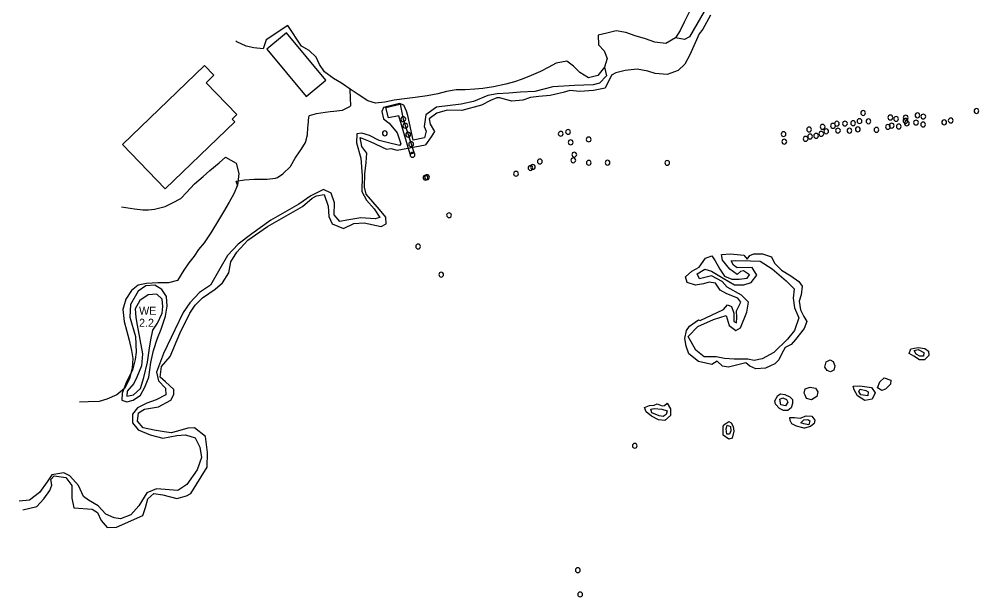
# Model space of a CAD drawing. Extents: x 2160437 to 2172832, y 205694 to 212444.
# Drawn here: x 2160437 to 2161037, y 210691 to 211052 of the extents above; entities that cross this region are included whole.
import ezdxf

# ---------------------------------------------------------------- set-up
doc = ezdxf.new("R2010")
doc.units = 0
for name, color, linetype in [('Default', 7, 'Continuous'), ('RD_EX_Bldg', 7, 'Continuous'), ('RD_EX_BldgApp', 7, 'Continuous'), ('RD_EX_Dam', 7, 'Continuous'), ('RD_EX_H2O', 7, 'Continuous'), ('RD_EX_H2O_Pond', 7, 'Continuous'), ('RD_EX_H2O_txCode', 7, 'Continuous'), ('RD_EX_Road_Post', 7, 'Continuous'), ('RD_EX_VEG_ShrubLine', 7, 'Continuous'), ('RD_EX_VEG_TreeLine', 7, 'Continuous')]:
    doc.layers.add(name, color=color, linetype=linetype)

# ---------------------------------------------------------------- blocks, each defined once
blk = doc.blocks.new('POST')
at = {"layer": 'Default'}
for start, end in [(90, 270), (270, 90)]:
    blk.add_arc((0, 0), 0.0417, start, end, dxfattribs=at)

msp = doc.modelspace()

# ---------------------------------------------------------------- linework, layer by layer
at = {"layer": 'RD_EX_Bldg'}
msp.add_lwpolyline([(2160501.36, 210973.72), (2160552.58, 211023.14), (2160558.56, 211016.94), (2160553.68, 211012.23), (2160572.82, 210992.39), (2160569.87, 210989.54), (2160571.52, 210987.83), (2160528.14, 210945.96)], close=True, dxfattribs=at)
at = {"layer": 'RD_EX_BldgApp'}
msp.add_lwpolyline([(2160591.54, 211033.38), (2160616.14, 211003.75), (2160628.41, 211013.91), (2160603.81, 211043.54)], close=True, dxfattribs=at)
at = {"layer": 'RD_EX_Dam'}
msp.add_lwpolyline([(2160665.9, 210996.74), (2160674.86, 210998.85), (2160676.88, 210989.52), (2160683.57, 210968.33), (2160681.23, 210967.59), (2160674.11, 210991.64), (2160667.59, 210990.28)], close=True, dxfattribs=at)
at = {"layer": 'RD_EX_H2O'}
for points in [[(2160868.85, 211054.5), (2160864.01, 211045.74), (2160861.74, 211042.89), (2160855.94, 211029.7), (2160852.83, 211023.99), (2160848.57, 211019.95), (2160841.71, 211017.45), (2160834.34, 211018.06), (2160829.6, 211019.63), (2160823.02, 211020.81), (2160815.45, 211019.96), (2160809.7, 211018.51), (2160806.97, 211016.96), (2160803.03, 211008.9), (2160795.67, 211007.37), (2160787.27, 211006.83), (2160780.89, 211007.46), (2160776.83, 211006.17), (2160768.71, 211004.35), (2160761.67, 211003.77), (2160756.27, 211003.09), (2160751.54, 211001.35), (2160744.74, 211000.78), (2160740.76, 211001.83), (2160737.25, 211002.9), (2160735.24, 211002.82), (2160731.34, 211001.23), (2160725.76, 210998.26), (2160713.38, 210994.95), (2160704.23, 210995.09), (2160697.93, 210993.2), (2160693.13, 210989.75), (2160693.61, 210986.47), (2160696.31, 210981.78), (2160694.27, 210978.42), (2160690.79, 210973.58)], [(2160439.11, 210745.33), (2160447.81, 210747.53), (2160452.24, 210752.19), (2160456, 210757.43), (2160457.31, 210760.83), (2160456.66, 210764.25), (2160458.64, 210766.72), (2160465.96, 210765.49), (2160469.83, 210760.6), (2160469.81, 210752.74), (2160470.94, 210746.67), (2160482.54, 210745.7), (2160485.88, 210743.73), (2160488.03, 210738.76), (2160491.77, 210734.23), (2160497.77, 210734.58), (2160514.12, 210741.77), (2160515.69, 210746.79), (2160517.21, 210752.3), (2160521, 210755.68), (2160526.7, 210754.72), (2160535.43, 210752.39), (2160541.41, 210754.2), (2160544.21, 210755.65), (2160554.34, 210772.02), (2160554.53, 210781.26), (2160553.3, 210791.2), (2160546.51, 210796.54), (2160542.19, 210796.35), (2160535.79, 210794.61), (2160531.79, 210793.59), (2160527.47, 210794.15), (2160521.27, 210795.16), (2160514.35, 210796.62), (2160510.71, 210800.87), (2160511.34, 210805.97), (2160515.24, 210808.32), (2160523.83, 210809.76), (2160531.71, 210814), (2160533.49, 210817.54), (2160533.47, 210820.56), (2160528.26, 210825.3), (2160524.96, 210828.24), (2160525.84, 210834.91), (2160531.19, 210841.23), (2160537.3, 210855.49), (2160543.39, 210868.31), (2160546.86, 210873.28), (2160551.36, 210877.96), (2160559.3, 210883.23), (2160564, 210887.35), (2160567.8, 210893.56), (2160569.05, 210900.41), (2160572.9, 210906.49), (2160579.81, 210913.95), (2160592.04, 210922.54), (2160613.97, 210935.03), (2160619.93, 210940.26), (2160622.57, 210941.61), (2160627.52, 210942.44), (2160629.93, 210935.1), (2160630.36, 210928.76), (2160632.34, 210924.05), (2160639.43, 210921.18), (2160645.94, 210924.43), (2160652.52, 210924.75), (2160663.14, 210922.37), (2160666.23, 210924.22), (2160665.96, 210928.34), (2160662.09, 210933.1), (2160653.6, 210942.62), (2160652.67, 210947.09), (2160652.83, 210955.36), (2160653.62, 210962.36), (2160654.13, 210968.21), (2160651.06, 210972.55), (2160649.9, 210978.06), (2160656.09, 210975.6), (2160666.29, 210970.75), (2160669.14, 210971.31), (2160673.11, 210970.09), (2160690.79, 210973.58)]]:
    msp.add_lwpolyline(points, dxfattribs=at)
for points in [[(2160903.23, 210833.84), (2160897.1, 210833.6), (2160893.47, 210835.1), (2160890.9, 210837.17), (2160880.15, 210834.53), (2160876.29, 210835.15), (2160873.04, 210838.33), (2160869.61, 210836.26), (2160861.35, 210837.98), (2160855.27, 210842.82), (2160853.58, 210847.61), (2160852.9, 210852.49), (2160853.87, 210857.52), (2160855.72, 210860.19), (2160861.28, 210864.22), (2160862.48, 210863.81), (2160876.88, 210870.53), (2160879.57, 210873.54), (2160882.04, 210872.42), (2160883.47, 210868.27), (2160883.52, 210863.15), (2160885.05, 210862.17), (2160885.33, 210865.48), (2160885.16, 210869.82), (2160887.9, 210875.12), (2160885.84, 210877.73), (2160879.1, 210880.44), (2160874.92, 210882.59), (2160871.99, 210886.99), (2160867.98, 210887.65), (2160864.37, 210886.65), (2160859.42, 210885.88), (2160854.26, 210887.46), (2160853.25, 210890.99), (2160857.22, 210894.57), (2160861.68, 210897.07), (2160865.82, 210902.64), (2160869.65, 210904.12), (2160871.75, 210901.08), (2160874.59, 210895.71), (2160877.67, 210891.33), (2160882.15, 210889.59), (2160886.78, 210889.64), (2160891.75, 210890.26), (2160893.13, 210892.24), (2160889.54, 210894.85), (2160887.54, 210894.39), (2160885.56, 210892.51), (2160880.86, 210895.82), (2160876.38, 210901.47), (2160875.76, 210904.88), (2160881.36, 210905.3), (2160889.63, 210904.57), (2160891.66, 210902.02), (2160893.46, 210904.28), (2160895.87, 210905.3), (2160901.4, 210905.31), (2160906.96, 210903.58), (2160908.85, 210899.45), (2160913.24, 210895.21), (2160918.95, 210891.69), (2160923.96, 210888.12), (2160926.14, 210885.25), (2160925.49, 210879.73), (2160924.34, 210875.79), (2160925.14, 210870.33), (2160927.17, 210866.31), (2160928.95, 210863.13), (2160927.35, 210858.79), (2160921.97, 210851.76), (2160919.33, 210848.61), (2160915.47, 210846.74), (2160913.47, 210843.16), (2160911.48, 210839.08), (2160909, 210836.67), (2160906.4, 210835.33)], [(2160993, 210843.11), (2160994.06, 210846.1), (2160998.52, 210846.86), (2161002.7, 210846.25), (2161005.08, 210844.59), (2161005.2, 210841.93), (2161002.48, 210839.11), (2160999.39, 210839.06), (2160995.94, 210841.43)], [(2160940.2, 210834.59), (2160941.14, 210837.81), (2160943.59, 210839.13), (2160945.43, 210838.07), (2160946.62, 210835.45), (2160946.01, 210832.71), (2160943.88, 210831.59), (2160941.66, 210832.42)], [(2160974.74, 210825.43), (2160977.34, 210827.96), (2160981.58, 210826.33), (2160981.32, 210823.84), (2160978.16, 210820.82), (2160975.82, 210820.02), (2160973.21, 210821.67)], [(2160927.44, 210818.24), (2160927.99, 210821.06), (2160931.05, 210821.94), (2160934.36, 210821.39), (2160936.01, 210819.02), (2160935.34, 210816.26), (2160931.98, 210814.13), (2160928.8, 210814.93), (2160927.92, 210817.01)], [(2160962.17, 210822.87), (2160969.42, 210821.76), (2160971.8, 210818.51), (2160969.77, 210814.48), (2160965.37, 210813.78), (2160960.67, 210816.57), (2160958.57, 210820.36), (2160957.96, 210822.6)], [(2160909.13, 210813.56), (2160911.01, 210816.82), (2160912.67, 210817.81), (2160915.27, 210817.47), (2160918.36, 210815.98), (2160920.04, 210814.32), (2160920.13, 210811.88), (2160919.27, 210809.15), (2160917.14, 210807.39), (2160914.46, 210807.36), (2160911.97, 210808.77), (2160909.44, 210811.48)], [(2160835.56, 210811.54), (2160838.55, 210810.47), (2160840.14, 210810.59), (2160841.75, 210812.03), (2160843.9, 210808.54), (2160843.86, 210804.3), (2160840.41, 210801.15), (2160836.32, 210801.58), (2160832.04, 210803.84), (2160828.75, 210806.6), (2160827.53, 210809.29), (2160830.73, 210810.6), (2160833.65, 210810.84)], [(2160927.44, 210796.5), (2160922.6, 210797.59), (2160919.72, 210799.04), (2160918.62, 210801.13), (2160918.43, 210803.01), (2160921.3, 210803.16), (2160924.85, 210802.74), (2160928.54, 210804.05), (2160932.26, 210803.96), (2160934.14, 210801.46), (2160933.56, 210799.23), (2160931.25, 210797.38), (2160927.56, 210796.45)], [(2160880.22, 210800.52), (2160881.84, 210799.67), (2160882.94, 210797.49), (2160883.35, 210794.44), (2160882.3, 210790.08), (2160880.27, 210789.64), (2160876.71, 210792), (2160876.82, 210797.6), (2160877.8, 210798.87)]]:
    msp.add_lwpolyline(points, close=True, dxfattribs=at)
at = {"layer": 'RD_EX_H2O_Pond'}
msp.add_lwpolyline([(2160526.57, 210872.54), (2160526.26, 210877.02), (2160522.92, 210880.13), (2160517.42, 210879.69), (2160512.18, 210876.25), (2160509.42, 210871.04), (2160509.75, 210865.62), (2160510.61, 210860.83), (2160513.95, 210842.93), (2160513.3, 210835.43), (2160510.43, 210828.19), (2160508.52, 210824.3), (2160504.28, 210819.54), (2160504.03, 210816.43), (2160508.21, 210817.15), (2160512.69, 210821.17), (2160514.71, 210828.05), (2160517.13, 210837.75), (2160518.36, 210846.34), (2160519.18, 210851.68), (2160520.43, 210857.63), (2160523.31, 210862.08), (2160526.21, 210868.27)], close=True, dxfattribs=at)
at = {"layer": 'RD_EX_VEG_ShrubLine'}
for points in [[(2160867.24, 211060.84), (2160855.8, 211040.94), (2160852.66, 211039.38), (2160846.9, 211040.46)], [(2160802.51, 211021.99), (2160803.81, 211016.54), (2160799.48, 211011.96), (2160795.6, 211010.94), (2160783.81, 211010.48), (2160770.23, 211009.79), (2160759.18, 211006.87), (2160750.08, 211006.47), (2160742.79, 211005.72), (2160735.57, 211005.39), (2160729.76, 211004.32), (2160720.67, 211000.5), (2160713.04, 210998.86), (2160697.67, 210997.02), (2160691.01, 210992.16), (2160689.93, 210985.05), (2160691.23, 210982.05), (2160690.11, 210977.94), (2160683.1, 210976.52), (2160680.72, 210986.97), (2160679.73, 210991.82), (2160678.78, 210994.45), (2160677.15, 210998.26), (2160674.41, 210999.38), (2160664.47, 210996.87), (2160663.37, 210994.3), (2160664.44, 210989.65), (2160668.02, 210987.04), (2160672.95, 210980.93), (2160675.29, 210974.08), (2160674.52, 210973.15), (2160666.73, 210975), (2160661.73, 210976.23), (2160655.8, 210979.26), (2160651.02, 210980.73), (2160647.75, 210980.29), (2160647.68, 210974.76), (2160650.32, 210965.11), (2160651.24, 210954.1), (2160650.91, 210944.29), (2160653.91, 210938.88), (2160658.67, 210933.53), (2160662.32, 210928.17), (2160659.28, 210927.35), (2160650.31, 210927.88), (2160641.54, 210926.41), (2160637.2, 210925.53), (2160633.74, 210929.65), (2160633.92, 210937.21), (2160631.82, 210943.32), (2160627.11, 210945.57), (2160619.02, 210941.64), (2160611.64, 210936.47), (2160594.03, 210926.49), (2160582.13, 210917.86), (2160573.75, 210911.52), (2160567.09, 210904.35), (2160562.31, 210895.97), (2160556.42, 210885.78), (2160549.51, 210881.26), (2160543.53, 210874.7), (2160539.39, 210868.76), (2160534.02, 210857.81), (2160526.99, 210843.04), (2160522.64, 210831.4), (2160523.94, 210825.95), (2160528.25, 210821.39), (2160528.54, 210817.32), (2160522.38, 210814.2), (2160516.63, 210812.11), (2160510.79, 210809.2), (2160507.74, 210805.14), (2160507.64, 210799.79), (2160511.23, 210795.33), (2160518.69, 210792.24), (2160526.59, 210790.23), (2160535.4, 210791.91), (2160540.86, 210792.34), (2160546.77, 210790.3), (2160549.69, 210784.46), (2160550.79, 210778.05), (2160547.98, 210770.46), (2160541.71, 210761.2), (2160535.97, 210757.37), (2160522.64, 210758.48), (2160516.55, 210755.91), (2160511.61, 210747.95), (2160506.52, 210742.33), (2160500.24, 210739.72), (2160496.18, 210740.35), (2160491.01, 210742.75), (2160486.3, 210747.95), (2160486.3, 210747.95), (2160480.27, 210751.38), (2160477.08, 210753.69), (2160473.82, 210760.55), (2160468.56, 210766.7), (2160464.66, 210768.58), (2160457.18, 210767.16), (2160454.29, 210762.96), (2160449.58, 210756.12), (2160443.24, 210751.35), (2160436.86, 210750.82)], [(2160573.36, 210948.21), (2160572.45, 210950.69), (2160577.7, 210951.67), (2160583.63, 210952.11), (2160590.63, 210952.07), (2160591.81, 210952), (2160596.96, 210952.63), (2160598.17, 210953), (2160601.69, 210955.29), (2160606.42, 210959.98), (2160606.55, 210960.39), (2160609.29, 210965.17), (2160612.54, 210969.78), (2160613.08, 210970.58), (2160615.74, 210974.93), (2160615.74, 210974.93), (2160617.02, 210979.8), (2160617.29, 210984.36), (2160617.39, 210985.59), (2160617.91, 210990.98), (2160618.21, 210991.77), (2160622.55, 210993.16), (2160622.55, 210993.16), (2160628, 210993.82), (2160631.27, 210994.37), (2160633.41, 210994.5), (2160638.79, 210995.13), (2160638.79, 210995.13), (2160643.54, 210997.56), (2160644.11, 210998.05), (2160643.81, 211002.76), (2160643.77, 211008.29)]]:
    msp.add_lwpolyline(points, dxfattribs=at)
for points in [[(2160899.8, 210900.89), (2160907.31, 210895.99), (2160916.13, 210888.59), (2160921.18, 210883.47), (2160920.44, 210877.67), (2160921.4, 210871.67), (2160923.95, 210865.42), (2160921.33, 210857.54), (2160917.04, 210852.03), (2160908.51, 210843.62), (2160901.16, 210839.68), (2160896.04, 210838.79), (2160892.23, 210839.57), (2160883.73, 210839.55), (2160877.56, 210839.89), (2160872.4, 210841), (2160864.86, 210841.02), (2160859.65, 210845.17), (2160854.94, 210853.72), (2160860.89, 210859.99), (2160870.62, 210864.37), (2160878.64, 210866.87), (2160880.61, 210860.59), (2160884.62, 210857.36), (2160887.67, 210859.1), (2160891.45, 210868.9), (2160892.56, 210875.1), (2160888.2, 210879.44), (2160879.23, 210884.63), (2160876.09, 210888.13), (2160869.41, 210891.72), (2160861.9, 210889.74), (2160860.56, 210892.8), (2160865.25, 210895.87), (2160869.38, 210894.57), (2160876.74, 210890.19), (2160883.91, 210886), (2160889.76, 210886), (2160894.17, 210887.4), (2160897.72, 210892.12), (2160894.96, 210896.86), (2160885.61, 210896.65), (2160883.32, 210898.26), (2160881.83, 210901.01), (2160884.78, 210901.28), (2160893.83, 210901.05)], [(2160506.43, 210873.61), (2160506.02, 210865.8), (2160509.6, 210853.75), (2160510.05, 210843.88), (2160509.33, 210839.34), (2160507.62, 210832.76), (2160503.87, 210825.36), (2160501.23, 210818.27), (2160501.05, 210813.9), (2160504.09, 210812.81), (2160508.15, 210813.98), (2160512.69, 210817.08), (2160515.33, 210822.03), (2160517.9, 210828.33), (2160519.08, 210837.47), (2160520.71, 210844.9), (2160523.24, 210852.67), (2160525.5, 210858.31), (2160528.36, 210866.4), (2160529.3, 210872.69), (2160528.88, 210878.67), (2160525.97, 210883), (2160521.66, 210885.88), (2160515.96, 210885.45), (2160511.3, 210881.94)], [(2160996.12, 210844.91), (2160998.68, 210845.55), (2161002.25, 210843.65), (2161001.96, 210841.32), (2160999.65, 210841.43), (2160997.4, 210842.73)], [(2160962.75, 210817.27), (2160961.55, 210819.41), (2160962.42, 210820.72), (2160965.99, 210820.04), (2160967.45, 210819.1), (2160967.08, 210816.62)], [(2160912.73, 210811.03), (2160912.24, 210814.55), (2160913.99, 210815.27), (2160916.33, 210814.4), (2160917.16, 210812.7), (2160915.67, 210810.45)], [(2160836.68, 210804.03), (2160832.22, 210806.05), (2160831.52, 210808.26), (2160833.65, 210808.8), (2160838.52, 210808.29), (2160841.67, 210807.34), (2160841.07, 210804.97), (2160839.31, 210803.78)], [(2160925.25, 210799.7), (2160927.21, 210801.54), (2160929.7, 210801.83), (2160931.01, 210800.96), (2160930.29, 210798.55), (2160927.12, 210799.04)], [(2160878.99, 210792.61), (2160878.59, 210796.1), (2160879.23, 210798.35), (2160881.31, 210797.51), (2160881.49, 210794.78), (2160880.76, 210792.75)]]:
    msp.add_lwpolyline(points, close=True, dxfattribs=at)
at = {"layer": 'RD_EX_VEG_TreeLine'}
for points in [[(2160855.5, 211056.38), (2160852.29, 211050.07), (2160849.79, 211045.06), (2160846.9, 211040.46), (2160840.85, 211036.83), (2160834.16, 211037.66), (2160828.23, 211039.65), (2160821.87, 211041.72), (2160815.9, 211043.61), (2160809.95, 211044.8), (2160804.15, 211043.26), (2160798.58, 211041.96), (2160798.86, 211035.92), (2160802.5, 211032.19), (2160804.29, 211027.44), (2160802.51, 211021.99), (2160798.46, 211016.88), (2160792.57, 211015.38), (2160787.2, 211018.62), (2160783.22, 211022.62), (2160779.13, 211025.86), (2160772.48, 211024.47), (2160767.39, 211021.92), (2160762.62, 211019.32), (2160756.86, 211016.84), (2160751.15, 211014.45), (2160746.29, 211012.94), (2160741.01, 211011.51), (2160741.01, 211011.51), (2160733.15, 211009.74), (2160726.57, 211008.78), (2160721.49, 211008.3), (2160715.61, 211007.84), (2160709.94, 211007.85), (2160703.98, 211006.73), (2160698.42, 211005.43), (2160691.81, 211004.14), (2160684.34, 211003), (2160679.36, 211002.48), (2160671.13, 211001.45), (2160665.37, 211000.24), (2160659.45, 210999.45), (2160654.67, 211000.91), (2160648.71, 211004.89), (2160643.77, 211008.29), (2160638.24, 211011.95), (2160633.31, 211014.87), (2160627.62, 211019.19), (2160624.49, 211023.63), (2160622.5, 211028.34), (2160618.09, 211032.54), (2160613.34, 211035.21), (2160604.81, 211048.09), (2160591.23, 211039.08), (2160589.29, 211033.53), (2160583.51, 211034.07), (2160578.6, 211035.25), (2160572.93, 211037.81), (2160572.15, 211038.4)], [(2160500.87, 210934.7), (2160508.85, 210933.4), (2160514.07, 210932.89), (2160517.75, 210932.85), (2160521.42, 210933.27), (2160528.01, 210935.03), (2160532.69, 210937.2), (2160537.88, 210939.95), (2160541.46, 210943.77), (2160546.35, 210949.2), (2160551.8, 210953.8), (2160556.04, 210957.55), (2160561.81, 210962.35), (2160565.88, 210965.72), (2160572.35, 210962.1), (2160574.16, 210955.6), (2160573.36, 210948.21), (2160570.96, 210942.92), (2160568.1, 210937.61), (2160564.45, 210931.62), (2160561.44, 210926.5), (2160556.55, 210918.52), (2160552.45, 210912.27), (2160548.97, 210908.17), (2160546.11, 210903.9), (2160542.96, 210899.77), (2160539.7, 210895.11), (2160535.88, 210888.73), (2160530.13, 210887.28), (2160523.42, 210887.31), (2160516.5, 210886.85), (2160511.29, 210885.85), (2160506.99, 210882.47), (2160503.56, 210876.96), (2160501.69, 210870.51), (2160502.53, 210863.18), (2160503.88, 210857.7), (2160505.58, 210851.49), (2160507.01, 210844.93), (2160507.91, 210840.01), (2160507.53, 210834.04), (2160505.71, 210827.22), (2160502.68, 210821.3), (2160497.83, 210817.24), (2160491.65, 210814.59), (2160486.84, 210813.18), (2160479.96, 210812.82), (2160474.58, 210812.71)]]:
    msp.add_lwpolyline(points, dxfattribs=at)

# ---------------------------------------------------------------- block references
at = {"layer": 'RD_EX_Road_Post', "xscale": 36, "yscale": 36}
for p in [(2160964.21, 210993.42), (2160998.17, 210991.94), (2161035.01, 210994.66), (2160676.88, 210989.52), (2160676.88, 210989.52), (2160678.17, 210985.43), (2160945.39, 210985.38), (2160947.84, 210986.7), (2160952.87, 210986.8), (2160957.96, 210987.04), (2160961.97, 210988.35), (2160967.52, 210988.22), (2160981.22, 210990.58), (2160982.05, 210985.51), (2160984.82, 210989.71), (2160990.7, 210988.49), (2160990.79, 210990.48), (2160991.54, 210986.9), (2160997.28, 210987.42), (2161001.69, 210986.18), (2161001.81, 210991.16), (2161014.89, 210987.56), (2161018.95, 210988.73), (2160665.35, 210980.69), (2160679.94, 210979.84), (2160775.26, 210980.42), (2160779.84, 210981.59), (2160914.5, 210980.2), (2160930.46, 210983.11), (2160938.08, 210980.35), (2160938.9, 210984.73), (2160941.18, 210981.96), (2160948.5, 210982.41), (2160955.66, 210982.35), (2160960.89, 210983.17), (2160972.52, 210982.88), (2160979.72, 210984.72), (2160986.49, 210984.95), (2160681.8, 210973.92), (2160781.46, 210975.06), (2160792.7, 210976.87), (2160914.96, 210975.48), (2160928.28, 210977.26), (2160931.08, 210978.72), (2160934.84, 210979.1), (2160783.72, 210967.38), (2160682.65, 210967.23), (2160762.21, 210963.11), (2160783.1, 210963.84), (2160792.77, 210962.3), (2160804.54, 210962.35), (2160841.83, 210962.2), (2160747.32, 210955.43), (2160756.32, 210959.06), (2160757.86, 210959.64), (2160690.78, 210952.96), (2160691.74, 210953.3), (2160705.47, 210929.5), (2160686.13, 210909.94), (2160700.59, 210892.39), (2160821.51, 210785.41), (2160785.97, 210707.69), (2160787.38, 210692.51)]:
    msp.add_blockref('POST', p, dxfattribs=at)

# ---------------------------------------------------------------- texts
at = {"layer": 'RD_EX_H2O_txCode'}
for s, p in [('WE', (2160511.78, 210867.27)), ('2.2', (2160511.78, 210859.77))]:
    msp.add_text(s, height=5, dxfattribs=at).set_placement(p)

doc.saveas('drawing.dxf')
